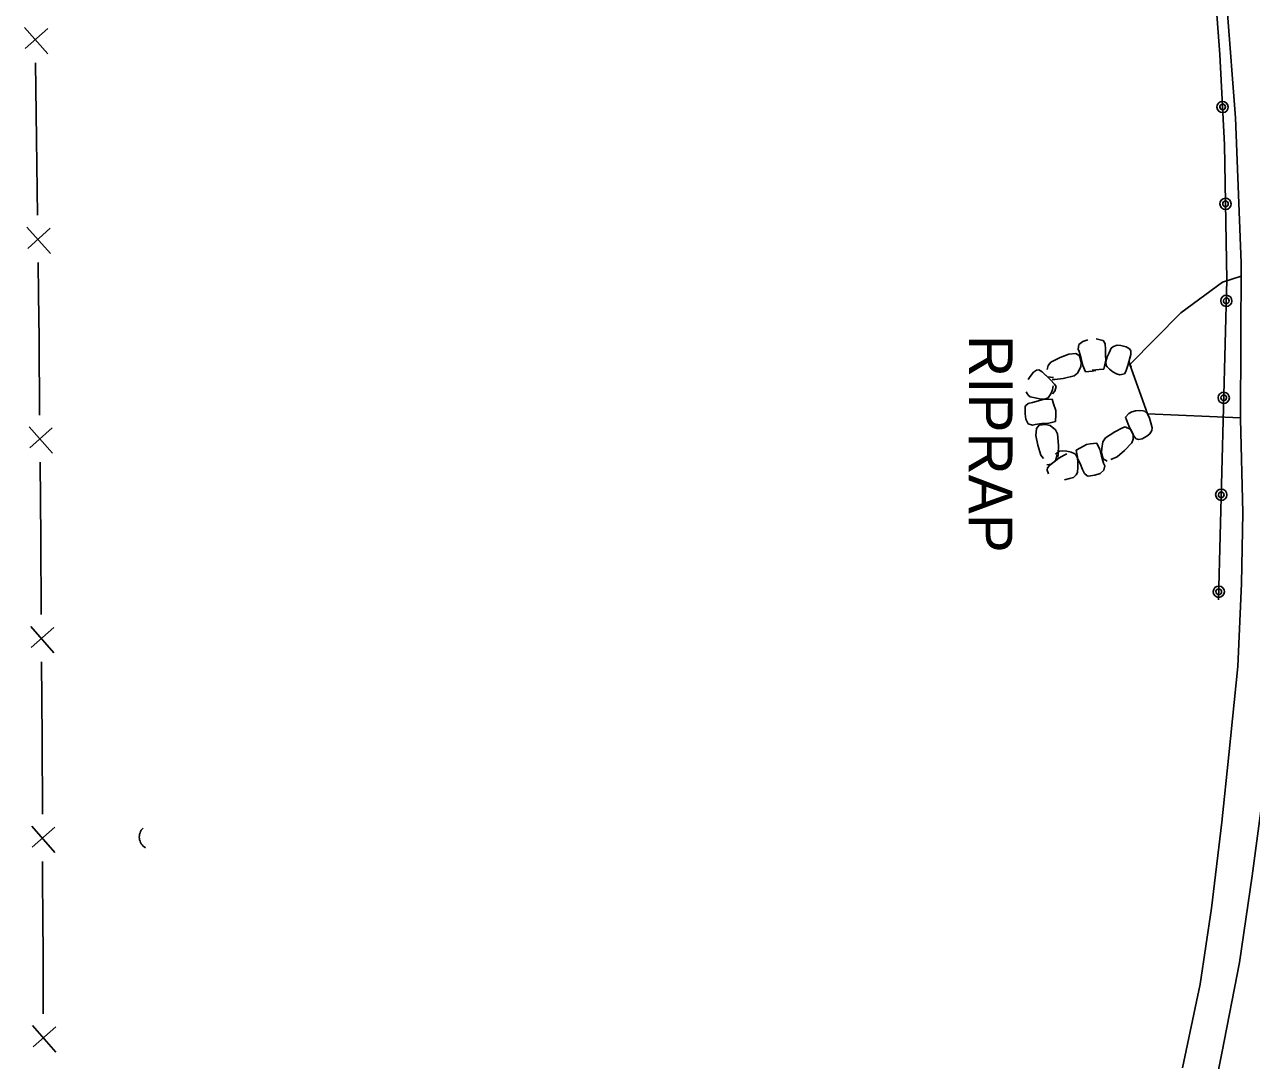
# Model space of a CAD drawing. Extents: x 588843 to 2552415, y 180129 to 269402.
# Drawn here: x 594113 to 594281.3, y 188090.9 to 188233 of the extents above; entities that cross this region are included whole.
import ezdxf

# ---------------------------------------------------------------- set-up
doc = ezdxf.new("R2010")
doc.units = 0
for name, color, linetype in [('E_BMGRD_P', 7, 'Continuous'), ('E_DRN', 7, 'Continuous'), ('E_DRN_RipRap', 7, 'Continuous'), ('E_DRN_RipRap_Text', 7, 'Continuous'), ('E_FEN_P', 7, 'Continuous'), ('E_RDWY', 7, 'Continuous'), ('E_RDWY_Gravel', 7, 'Continuous')]:
    doc.layers.add(name, color=color, linetype=linetype)

# ---------------------------------------------------------------- blocks, each defined once
blk = doc.blocks.new('RIPRT')
at = {"layer": 'E_DRN_RipRap_Text'}
blk.add_text('RIPRAP', height=12, dxfattribs=at).set_placement((-0.14, -3.59))
blk = doc.blocks.new('CULV2')
at = {"layer": 'E_DRN'}
blk.add_arc((19.7, 14.8), 24.6, 216.8699, 323.1301, dxfattribs=at)

msp = doc.modelspace()

# ---------------------------------------------------------------- linework, layer by layer
at = {"layer": 'E_BMGRD_P'}
msp.add_lwpolyline([(594276.82, 188154.07), (594277.95, 188197.94), (594277.64, 188216.48), (594276.99, 188228.87), (594276.03, 188241.75)], dxfattribs=at)
for centre, major_axis, ratio in [((594277.37, 188221.67), (0.04, -0.774), 0.993369), ((594277.37, 188221.67), (0.02, -0.39), 0.993369), ((594277.77, 188208.38), (0.013, -0.775), 0.993497), ((594277.77, 188208.38), (0.007, -0.39), 0.993497), ((594277.88, 188195.08), (-0.023, -0.774), 0.99367), ((594277.88, 188195.08), (-0.012, -0.39), 0.99367), ((594277.53, 188181.78), (-0.023, -0.774), 0.99367), ((594277.53, 188181.78), (-0.012, -0.39), 0.99367), ((594277.19, 188168.48), (-0.023, -0.774), 0.99367), ((594277.19, 188168.48), (-0.012, -0.39), 0.99367), ((594276.85, 188155.18), (-0.023, -0.774), 0.99367), ((594276.85, 188155.18), (-0.012, -0.39), 0.99367)]:
    msp.add_ellipse(centre, major_axis=major_axis, ratio=ratio, dxfattribs=at)
at = {"layer": 'E_DRN_RipRap'}
for p, q in [((594257.66, 188189.07), (594257.55, 188188.45)), ((594257.55, 188188.45), (594257.69, 188188.11)), ((594258.19, 188189.5), (594257.66, 188189.07)), ((594258.88, 188189.72), (594258.19, 188189.5)), ((594260.95, 188189.65), (594260.04, 188189.88)), ((594261.08, 188189.57), (594260.95, 188189.65)), ((594261.28, 188189.13), (594261.08, 188189.57)), ((594261.29, 188188.5), (594261.28, 188189.13)), ((594261.32, 188187.63), (594261.29, 188188.5)), ((594261.8, 188187.97), (594262.1, 188188.6)), ((594262.1, 188188.6), (594262.4, 188188.84)), ((594262.4, 188188.84), (594262.89, 188189.01)), ((594262.89, 188189.01), (594263.43, 188188.94)), ((594263.43, 188188.94), (594264.14, 188188.79)), ((594264.14, 188188.79), (594264.59, 188188.52)), ((594264.59, 188188.52), (594264.78, 188188.24)), ((594253.82, 188186.66), (594255.09, 188187.32)), ((594255.09, 188187.32), (594256.29, 188187.77)), ((594256.29, 188187.77), (594257.23, 188187.84)), ((594257.23, 188187.84), (594257.74, 188187.52)), ((594257.69, 188188.11), (594257.99, 188187.16)), ((594257.74, 188187.52), (594257.96, 188186.68)), ((594257.99, 188187.16), (594258.2, 188186.21)), ((594261.09, 188185.71), (594261.35, 188186.95)), ((594261.35, 188186.95), (594261.32, 188187.63)), ((594261.34, 188186.74), (594261.53, 188187.38)), ((594261.4, 188186.19), (594261.34, 188186.74)), ((594261.53, 188187.38), (594261.8, 188187.97)), ((594264.77, 188187.74), (594264.37, 188186.2)), ((594264.71, 188187.51), (594264.5, 188186.77)), ((594264.84, 188185.98), (594264.5, 188186.77)), ((594264.78, 188188.24), (594264.77, 188187.74)), ((594250.98, 188184.72), (594251.43, 188185.29)), ((594251.43, 188185.29), (594251.86, 188185.56)), ((594251.86, 188185.56), (594252.18, 188185.6)), ((594252.18, 188185.6), (594252.61, 188185.36)), ((594252.61, 188185.36), (594253.76, 188184.26)), ((594252.78, 188185.19), (594253.34, 188184.65)), ((594253.46, 188186.23), (594253.29, 188185.65)), ((594253.82, 188186.66), (594253.46, 188186.23)), ((594257.49, 188185.16), (594257, 188184.8)), ((594257.92, 188186.01), (594257.49, 188185.16)), ((594257.96, 188186.68), (594257.92, 188186.01)), ((594258.2, 188186.21), (594258.57, 188185.34)), ((594258.57, 188185.34), (594259.47, 188185.43)), ((594259.47, 188185.43), (594260, 188185.53)), ((594259.48, 188185.59), (594260.44, 188185.68)), ((594260.44, 188185.68), (594261.09, 188185.71)), ((594261.52, 188186.05), (594261.4, 188186.19)), ((594261.84, 188185.71), (594261.52, 188186.05)), ((594262.32, 188185.33), (594261.84, 188185.71)), ((594262.8, 188185.09), (594262.32, 188185.33)), ((594263.26, 188184.95), (594262.8, 188185.09)), ((594264.08, 188185.41), (594263.93, 188185.05)), ((594264.37, 188186.2), (594264.08, 188185.41)), ((594250.68, 188184.27), (594250.98, 188184.72)), ((594254.16, 188184.58), (594253.34, 188184.65)), ((594253.76, 188184.26), (594254.32, 188183.63)), ((594254.38, 188184.28), (594253.98, 188184.28)), ((594254.15, 188183.41), (594254.04, 188182.89)), ((594254.32, 188183.63), (594254.56, 188183.32)), ((594255.52, 188184.45), (594254.38, 188184.28)), ((594257, 188184.8), (594255.52, 188184.45)), ((594263.93, 188185.05), (594263.26, 188184.95)), ((594250.69, 188182.16), (594250.41, 188182.61)), ((594250.99, 188181.92), (594250.69, 188182.16)), ((594251.66, 188181.77), (594250.99, 188181.92)), ((594252.28, 188181.64), (594251.66, 188181.77)), ((594253.45, 188181.78), (594252.94, 188181.59)), ((594253.55, 188181.93), (594253.45, 188181.78)), ((594253.8, 188182.32), (594253.55, 188181.93)), ((594254.04, 188182.89), (594253.8, 188182.32)), ((594254.35, 188182.67), (594254.03, 188182.33)), ((594254.56, 188183.32), (594254.35, 188182.67)), ((594250.32, 188180.69), (594250.27, 188180.54)), ((594250.27, 188180.54), (594250.27, 188179.59)), ((594250.68, 188180.99), (594250.32, 188180.69)), ((594251.28, 188181.14), (594250.68, 188180.99)), ((594252.1, 188181.36), (594251.28, 188181.14)), ((594252.74, 188181.55), (594252.1, 188181.36)), ((594252.94, 188181.59), (594252.28, 188181.64)), ((594253.98, 188181.58), (594252.74, 188181.55)), ((594254.16, 188180.95), (594253.98, 188181.58)), ((594254.48, 188180.02), (594254.16, 188180.95)), ((594254.49, 188179.47), (594254.48, 188180.02)), ((594265.43, 188179.99), (594266.03, 188180.03)), ((594266.03, 188180.03), (594266.48, 188179.99)), ((594250.27, 188179.59), (594250.37, 188178.84)), ((594250.37, 188178.84), (594250.71, 188178.23)), ((594253.55, 188178.29), (594254.44, 188178.53)), ((594254.44, 188178.53), (594254.49, 188179.47)), ((594264.07, 188179.11), (594264.5, 188179.64)), ((594264.19, 188178.74), (594264.07, 188179.11)), ((594264.5, 188177.95), (594264.19, 188178.74)), ((594264.5, 188179.64), (594264.92, 188179.85)), ((594264.92, 188179.85), (594265.43, 188179.99)), ((594266.48, 188179.99), (594266.66, 188179.97)), ((594266.66, 188179.97), (594267.07, 188179.59)), ((594267.07, 188179.59), (594267.34, 188178.98)), ((594267.34, 188178.98), (594267.53, 188178.36)), ((594267.53, 188178.36), (594267.72, 188177.68)), ((594250.71, 188178.23), (594251.29, 188178.01)), ((594251.29, 188178.01), (594251.64, 188178.1)), ((594251.64, 188178.1), (594252.6, 188178.24)), ((594251.77, 188176.61), (594251.84, 188177.57)), ((594251.84, 188177.57), (594252.22, 188178.04)), ((594252.22, 188178.04), (594253.06, 188178.13)), ((594252.6, 188178.24), (594253.55, 188178.29)), ((594253.06, 188178.13), (594253.71, 188177.98)), ((594253.71, 188177.98), (594254.46, 188177.39)), ((594254.46, 188177.39), (594254.73, 188176.82)), ((594254.73, 188176.82), (594254.85, 188175.25)), ((594261.31, 188176.27), (594262.6, 188177.11)), ((594262.6, 188177.11), (594263.63, 188177.66)), ((594263.63, 188177.66), (594264.01, 188177.79)), ((594264.01, 188177.79), (594264.77, 188177.43)), ((594265.21, 188176.51), (594264.5, 188177.95)), ((594265.1, 188176.73), (594264.77, 188177.43)), ((594265.12, 188176.12), (594265.1, 188176.73)), ((594267.41, 188176.83), (594266.97, 188176.52)), ((594267.66, 188177.3), (594267.41, 188176.83)), ((594267.72, 188177.68), (594267.66, 188177.3)), ((594252.02, 188175.3), (594251.77, 188176.61)), ((594252.46, 188173.89), (594252.02, 188175.3)), ((594254.85, 188175.25), (594254.84, 188174.05)), ((594258.7, 188175.37), (594257.86, 188174.9)), ((594259.23, 188175.47), (594258.7, 188175.37)), ((594260.14, 188175.57), (594259.23, 188175.47)), ((594260.53, 188174.71), (594260.14, 188175.57)), ((594260.81, 188174.81), (594260.96, 188175.76)), ((594260.96, 188175.76), (594261.31, 188176.27)), ((594264.91, 188175.59), (594263.92, 188174.53)), ((594264.91, 188175.59), (594265.12, 188176.12)), ((594265.53, 188176.13), (594265.21, 188176.51)), ((594265.84, 188176.06), (594265.53, 188176.13)), ((594266.35, 188176.16), (594265.84, 188176.06)), ((594266.97, 188176.52), (594266.35, 188176.16)), ((594252.46, 188173.89), (594252.82, 188173.45)), ((594253.66, 188172.56), (594254.93, 188173.48)), ((594254.43, 188174.07), (594255.01, 188174.44)), ((594254.69, 188173.96), (594254.47, 188173.14)), ((594254.84, 188174.05), (594254.78, 188173.65)), ((594254.93, 188173.48), (594255.65, 188173.91)), ((594255.01, 188174.44), (594255.48, 188174.5)), ((594255.48, 188174.5), (594256.01, 188174.47)), ((594255.65, 188173.91), (594255.99, 188174.09)), ((594256.01, 188174.47), (594256.6, 188174.31)), ((594256.6, 188174.31), (594257.02, 188174.13)), ((594257.02, 188174.13), (594257.18, 188174.05)), ((594257.18, 188174.05), (594257.45, 188173.56)), ((594257.86, 188174.9), (594257.28, 188174.61)), ((594257.28, 188174.61), (594257.52, 188173.37)), ((594257.45, 188173.56), (594257.52, 188172.89)), ((594257.52, 188173.37), (594257.82, 188172.75)), ((594260.75, 188173.76), (594260.53, 188174.71)), ((594261.05, 188172.81), (594260.75, 188173.76)), ((594260.77, 188174.24), (594260.81, 188174.92)), ((594261.01, 188173.41), (594260.77, 188174.24)), ((594261.52, 188173.09), (594261.01, 188173.41)), ((594262.91, 188173.69), (594262.05, 188173.31)), ((594263.92, 188174.53), (594262.91, 188173.69)), ((594253.26, 188172.59), (594253.85, 188172.7)), ((594253.32, 188171.85), (594253.34, 188172.18)), ((594253.51, 188171.36), (594253.32, 188171.85)), ((594253.34, 188172.18), (594253.66, 188172.56)), ((594253.85, 188172.7), (594254.47, 188173.14)), ((594257.51, 188172.25), (594257.48, 188171.54)), ((594257.52, 188172.89), (594257.51, 188172.25)), ((594257.82, 188172.75), (594258.17, 188171.96)), ((594258.17, 188171.96), (594258.43, 188171.38)), ((594260.56, 188171.41), (594261.09, 188171.85)), ((594261.2, 188172.47), (594261.05, 188172.81)), ((594261.09, 188171.85), (594261.2, 188172.47)), ((594256.39, 188170.69), (594255.68, 188170.55)), ((594256.91, 188170.84), (594256.39, 188170.69)), ((594257.3, 188171.2), (594256.91, 188170.84)), ((594257.48, 188171.54), (594257.3, 188171.2)), ((594258.43, 188171.38), (594258.78, 188171.06)), ((594258.78, 188171.06), (594258.93, 188171.03)), ((594258.93, 188171.03), (594259.85, 188171.19)), ((594259.85, 188171.19), (594260.56, 188171.41))]:
    msp.add_line(p, q, dxfattribs=at)
at = {"layer": 'E_FEN_P'}
for p, q in [((594113.03, 188232.58), (594116.22, 188228.95)), ((594116.21, 188232.42), (594113.11, 188229.67)), ((594113.37, 188205.18), (594116.59, 188201.58)), ((594116.55, 188205.06), (594113.48, 188202.27)), ((594113.65, 188177.8), (594116.86, 188174.19)), ((594116.83, 188177.66), (594113.74, 188174.9)), ((594113.88, 188150.42), (594117.07, 188146.8)), ((594117.06, 188150.27), (594113.96, 188147.52)), ((594114.02, 188123.04), (594117.21, 188119.41)), ((594117.2, 188122.89), (594114.1, 188120.13)), ((594114.13, 188095.66), (594117.32, 188092.02)), ((594117.31, 188095.5), (594114.21, 188092.75))]:
    msp.add_line(p, q, dxfattribs=at)
for points in [[(594114.52, 188227.72), (594114.67, 188217.26)], [(594114.67, 188217.26), (594114.81, 188206.81)], [(594114.91, 188200.34), (594114.97, 188195.94), (594115.02, 188189.88)], [(594115.02, 188189.88), (594115.1, 188179.42)], [(594115.16, 188172.95), (594115.25, 188162.5)], [(594115.25, 188162.5), (594115.33, 188152.04)], [(594115.37, 188145.57), (594115.43, 188135.11)], [(594115.43, 188135.11), (594115.48, 188124.66)], [(594115.51, 188118.18), (594115.56, 188108.05), (594115.57, 188107.73)], [(594115.57, 188107.73), (594115.6, 188097.27)]]:
    msp.add_lwpolyline(points, dxfattribs=at)
at = {"layer": 'E_RDWY'}
for points in [[(594274.5, 188078.06), (594277.28, 188091.89), (594279.68, 188104.33), (594281.41, 188116.21), (594283.18, 188129.23), (594284.47, 188141.37), (594285.89, 188155.36), (594286.91, 188169.36), (594287.39, 188181.9), (594287.55, 188193.97), (594287.49, 188205.04), (594287.2, 188215.4), (594286.48, 188227.09), (594285.71, 188238.87), (594284.68, 188249.85), (594282.81, 188262.87), (594280.4, 188274.68), (594277.26, 188286.5), (594273.44, 188299.59), (594268.99, 188312.4), (594262.07, 188329.72), (594256.6, 188342.56), (594251.93, 188353.55), (594249.5, 188358.65)], [(594279.84, 188179.03), (594267.08, 188179.57), (594264.67, 188186.36), (594271.63, 188193.42), (594277.37, 188197.63), (594279.92, 188198.46)]]:
    msp.add_lwpolyline(points, dxfattribs=at)
at = {"layer": 'E_RDWY_Gravel'}
msp.add_lwpolyline([(594271.88, 188089.88), (594274.28, 188101.34), (594275.86, 188111.76), (594277.28, 188123.56), (594278.24, 188132.8), (594279.48, 188144.92), (594279.97, 188156.32), (594280.16, 188166), (594279.84, 188178.9), (594279.93, 188200.3), (594279.16, 188220.18), (594278, 188235.08), (594276.71, 188248.55), (594274.98, 188265.62), (594272.74, 188279.72), (594270.31, 188292.38), (594267.17, 188304.23), (594262.56, 188318.31), (594254.88, 188337.92), (594249.88, 188350.97), (594249.76, 188351.26)], dxfattribs=at)

# ---------------------------------------------------------------- block references
at = {"layer": 'E_DRN', "xscale": 0.0692180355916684, "yscale": 0.0692180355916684, "rotation": -83.39145092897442}
msp.add_blockref('CULV2', (594129.3, 188122.77), dxfattribs=at)
at = {"layer": 'E_DRN_RipRap_Text', "xscale": 0.5, "yscale": 0.5000000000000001, "rotation": -90.05957280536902}
msp.add_blockref('RIPRT', (594244.37, 188190.33), dxfattribs=at)

doc.saveas('drawing.dxf')
